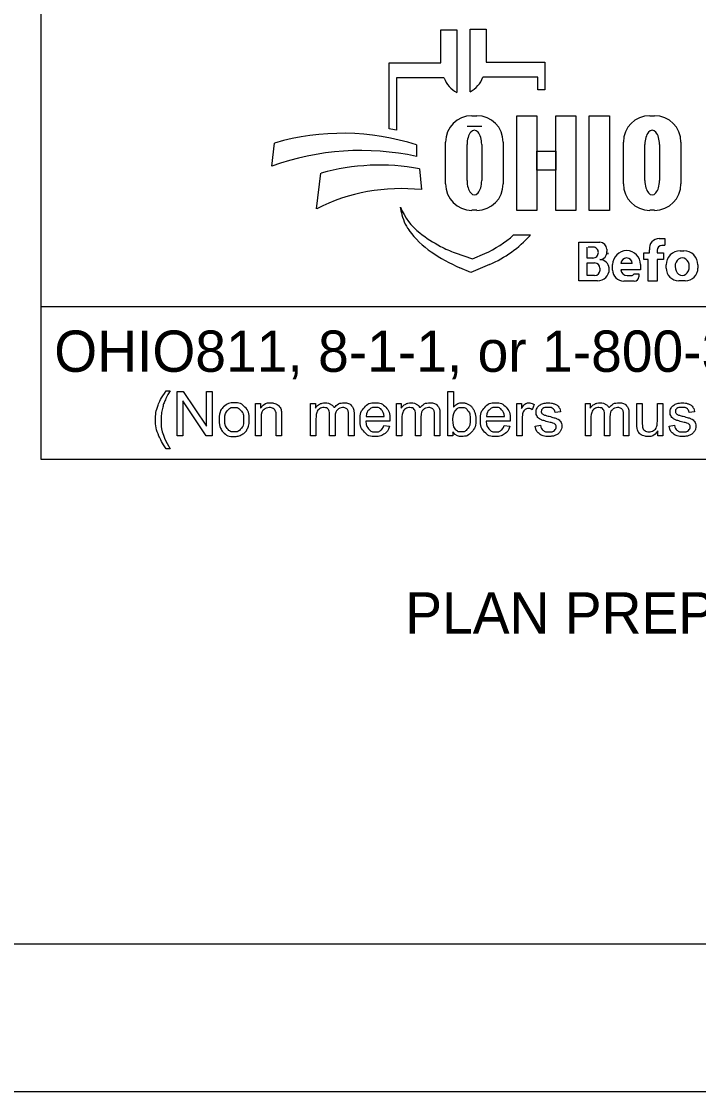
# Model space of a CAD drawing. Extents: x 0 to 81.5, y 0 to 35.2.
# Drawn here: x 2.311 to 4.607, y 0 to 3.629 of the extents above; entities that cross this region are included whole.
import ezdxf

# ---------------------------------------------------------------- set-up
doc = ezdxf.new("R2010")
doc.units = 0
for name, color, linetype in [('SH_Border', 7, 'Continuous'), ('SH_Cut_Line', 7, 'Continuous'), ('SH_Data', 7, 'Continuous'), ('SH_Text', 7, 'Continuous')]:
    doc.layers.add(name, color=color, linetype=linetype)

msp = doc.modelspace()

# ---------------------------------------------------------------- linework, layer by layer
at = {"layer": 'SH_Border'}
msp.add_lwpolyline([(1.5, 21.5), (33.5, 21.5), (33.5, 0.5), (1.5, 0.5)], close=True, dxfattribs=at)
at = {"layer": 'SH_Cut_Line'}
msp.add_lwpolyline([(0, 0), (34, 0), (34, 22), (0, 22)], close=True, dxfattribs=at)
at = {"layer": 'SH_Data'}
for p, q in [((2.3775, 2.1428), (2.3775, 4.4803)), ((6.6275, 2.6607), (2.3775, 2.6607)), ((6.6275, 2.1428), (2.3775, 2.1428))]:
    msp.add_line(p, q, dxfattribs=at)
at = {"layer": 'SH_Text'}
for p, q in [((3.7335, 3.4883), (3.7335, 3.5998)), ((3.7335, 3.5998), (3.7872, 3.5998)), ((3.7872, 3.5998), (3.7872, 3.3877)), ((3.8329, 3.39), (3.8329, 3.6021)), ((3.8329, 3.6021), (3.8865, 3.6021)), ((3.8865, 3.6021), (3.8865, 3.4906)), ((3.5576, 3.2644), (3.5576, 3.4883)), ((3.5576, 3.4883), (3.7335, 3.4883)), ((3.8865, 3.4906), (4.0857, 3.4906)), ((4.0857, 3.4906), (4.0857, 3.3968)), ((3.5828, 3.4369), (3.5828, 3.26)), ((3.7439, 3.4369), (3.5828, 3.4369)), ((4.0625, 3.4392), (3.8761, 3.4392)), ((4.0625, 3.3968), (4.0625, 3.4392)), ((4.0857, 3.3968), (4.0625, 3.3968)), ((3.8385, 3.3091), (3.8551, 3.3091)), ((4.4416, 3.3091), (4.4581, 3.3091)), ((3.8718, 3.2721), (3.822, 3.2721)), ((3.1602, 3.1381), (3.1696, 3.2162)), ((3.6509, 3.2097), (3.6509, 3.1709)), ((3.7491, 3.0776), (3.7491, 3.2196)), ((3.822, 3.089), (3.822, 3.2114)), ((3.8718, 3.2114), (3.8718, 3.089)), ((3.9445, 3.2196), (3.9445, 3.0776)), ((4.3521, 3.0776), (4.3521, 3.2196)), ((4.425, 3.089), (4.425, 3.2114)), ((4.4748, 3.2114), (4.4748, 3.089)), ((4.5476, 3.2196), (4.5476, 3.0776)), ((3.6608, 3.1291), (3.6671, 3.0582)), ((3.312, 2.9936), (3.3267, 3.1137)), ((3.5997, 2.9807), (3.5967, 2.9986)), ((3.8551, 2.9882), (3.8385, 2.9882)), ((4.4581, 2.9882), (4.4416, 2.9882)), ((3.98, 2.9048), (4.0375, 2.9048)), ((4.2013, 2.749), (4.2013, 2.8798)), ((4.2013, 2.8798), (4.2725, 2.8798)), ((4.4739, 2.8926), (4.4934, 2.8926)), ((4.4934, 2.8691), (4.4832, 2.8691)), ((4.4934, 2.8926), (4.4934, 2.8696)), ((3.7816, 2.8444), (3.841, 2.8239)), ((3.841, 2.8239), (3.8821, 2.8417)), ((4.2293, 2.8263), (4.2293, 2.8632)), ((4.2545, 2.8632), (4.2332, 2.8632)), ((4.2963, 2.856), (4.2963, 2.8481)), ((4.4213, 2.8212), (4.4213, 2.8442)), ((4.4213, 2.8442), (4.4406, 2.8442)), ((4.4406, 2.8442), (4.4406, 2.8546)), ((4.4667, 2.8526), (4.4667, 2.8442)), ((4.4667, 2.8442), (4.4883, 2.8442)), ((4.4883, 2.8442), (4.4883, 2.8212)), ((4.5451, 2.8508), (4.5573, 2.8508)), ((3.8983, 2.8044), (3.835, 2.7769)), ((4.2487, 2.8263), (4.2293, 2.8263)), ((4.2293, 2.7669), (4.2293, 2.8097)), ((4.2293, 2.8097), (4.2548, 2.8097)), ((4.3159, 2.7858), (4.3159, 2.8042)), ((4.3824, 2.8082), (4.3439, 2.8082)), ((4.4104, 2.8042), (4.4104, 2.7866)), ((4.4362, 2.8212), (4.4213, 2.8212)), ((4.4362, 2.7478), (4.4362, 2.8212)), ((4.4883, 2.8212), (4.4667, 2.8212)), ((4.4667, 2.8212), (4.4667, 2.7478)), ((4.4973, 2.7922), (4.4973, 2.8029)), ((4.6051, 2.8029), (4.6051, 2.7922)), ((3.835, 2.7769), (3.7976, 2.7934)), ((4.2546, 2.7669), (4.2293, 2.7669)), ((4.2729, 2.7916), (4.2729, 2.7853)), ((4.3043, 2.7887), (4.3043, 2.7884)), ((4.4104, 2.7866), (4.344, 2.7866)), ((4.3649, 2.7673), (4.379, 2.7673)), ((4.3876, 2.7729), (4.4045, 2.7729)), ((4.4045, 2.7729), (4.4045, 2.7631)), ((4.265, 2.749), (4.2013, 2.749)), ((4.3892, 2.7478), (4.3538, 2.7478)), ((4.4667, 2.7478), (4.4362, 2.7478)), ((4.5623, 2.7494), (4.5401, 2.7494))]:
    msp.add_line(p, q, dxfattribs=at)
for points in [[(3.991, 3.3081), (4.0589, 3.3081), (4.0589, 2.9881), (3.991, 2.9881)], [(4.1231, 3.3081), (4.1911, 3.3081), (4.1911, 2.9881), (4.1231, 2.9881)], [(4.2364, 3.3081), (4.3052, 3.3081), (4.3052, 2.9881), (4.2364, 2.9881)], [(4.0589, 3.1882), (4.1231, 3.1882), (4.1231, 3.1242), (4.0589, 3.1242)]]:
    msp.add_lwpolyline(points, close=True, dxfattribs=at)
for points in [[(2.8021, 2.3766), (2.8153, 2.3766)], [(2.8389, 2.2239), (2.8389, 2.3741), (2.8592, 2.3741), (2.9382, 2.2561), (2.9382, 2.3741), (2.9572, 2.3741), (2.9572, 2.2239), (2.9369, 2.2239), (2.8579, 2.3419), (2.8579, 2.2239), (2.8389, 2.2239)], [(3.7743, 2.2239), (3.7573, 2.2239), (3.7573, 2.3741), (3.7757, 2.3741), (3.7757, 2.3206)], [(3.1048, 2.2239), (3.1048, 2.3328), (3.1214, 2.3328), (3.1214, 2.3173)], [(3.2912, 2.2239), (3.2912, 2.3328), (3.3077, 2.3328), (3.3077, 2.3174)], [(3.5826, 2.2239), (3.5826, 2.3328), (3.5991, 2.3328), (3.5991, 2.3174)], [(3.9904, 2.2239), (3.9904, 2.3328), (4.007, 2.3328), (4.007, 2.3163)], [(4.0495, 2.3293), (4.043, 2.3122)], [(4.2236, 2.2239), (4.2236, 2.3328), (4.2401, 2.3328), (4.2401, 2.3174)], [(4.3979, 2.2654), (4.3979, 2.3328), (4.4164, 2.3328), (4.4164, 2.2724)], [(4.4676, 2.2745), (4.4676, 2.3328), (4.4861, 2.3328), (4.4861, 2.2239), (4.4696, 2.2239)], [(3.1932, 2.2908), (3.1932, 2.2239), (3.1748, 2.2239), (3.1748, 2.2901)], [(3.3743, 2.2871), (3.3743, 2.2239), (3.3559, 2.2239), (3.3559, 2.2946)], [(3.4388, 2.2986), (3.4388, 2.2239), (3.4203, 2.2239), (3.4203, 2.2924)], [(3.4799, 2.2887), (3.5406, 2.2887)], [(3.6657, 2.2871), (3.6657, 2.2239), (3.6473, 2.2239), (3.6473, 2.2946)], [(3.7301, 2.2986), (3.7301, 2.2239), (3.7117, 2.2239), (3.7117, 2.2924)], [(3.8879, 2.2887), (3.9486, 2.2887)], [(4.1394, 2.3046), (4.1213, 2.3022)], [(4.3067, 2.2871), (4.3067, 2.2239), (4.2883, 2.2239), (4.2883, 2.2946)], [(4.3711, 2.2986), (4.3711, 2.2239), (4.3527, 2.2239), (4.3527, 2.2924)], [(4.594, 2.3046), (4.5759, 2.3022)], [(3.1233, 2.2833), (3.1233, 2.2239), (3.1048, 2.2239)], [(3.3097, 2.2803), (3.3097, 2.2239), (3.2912, 2.2239)], [(3.56, 2.2736), (3.4788, 2.2736)], [(3.5404, 2.2591), (3.5595, 2.2567)], [(3.601, 2.2803), (3.601, 2.2239), (3.5826, 2.2239)], [(3.968, 2.2736), (3.8868, 2.2736)], [(3.9484, 2.2591), (3.9675, 2.2567)], [(4.0088, 2.2809), (4.0088, 2.2239), (3.9904, 2.2239)], [(4.053, 2.2564), (4.0712, 2.2593)], [(4.242, 2.2803), (4.242, 2.2239), (4.2236, 2.2239)], [(4.5076, 2.2564), (4.5258, 2.2593)], [(3.7743, 2.2375), (3.7743, 2.2239)], [(4.4696, 2.2239), (4.4696, 2.24)], [(2.8153, 2.1798), (2.8021, 2.1798)]]:
    msp.add_lwpolyline(points, dxfattribs=at)
for centre, radius, start, end in [((3.8353, 3.4736), 0.0985, 201.9296, 240.7469), ((3.7847, 3.476), 0.0985, 299.2531, 338.0704), ((3.8385, 3.2196), 0.0895, 90, 180), ((3.8551, 3.2196), 0.0895, 0, 90), ((4.4416, 3.2196), 0.0895, 90, 180), ((4.4581, 3.2196), 0.0895, 0, 90), ((3.3997, 2.4302), 0.8191, 72.1402, 106.3144), ((3.4295, 2.4554), 0.8191, 79.2074, 81.0007), ((3.4628, 2.2991), 0.8919, 77.8238, 109.8274), ((3.5267, 2.4094), 0.7322, 79.44, 105.8467), ((3.5987, 2.4262), 0.6357, 83.8248, 116.8021), ((3.8385, 3.0776), 0.0895, 180, 270), ((3.8551, 3.0776), 0.0895, 270, 0), ((4.4416, 3.0776), 0.0895, 180, 270), ((4.4581, 3.0776), 0.0895, 270, 0), ((3.7841, 3.0707), 0.2008, 201.0457, 232.5314), ((3.741, 3.0048), 0.1433, 189.6817, 216.0884), ((3.8747, 3.1022), 0.3088, 216.0884, 235.7167), ((3.9766, 3.3219), 0.5173, 232.5314, 241.794), ((3.7387, 3.1722), 0.3602, 293.4582, 312.0712), ((3.7387, 3.1722), 0.401, 293.4582, 317.8286), ((4.2725, 2.856), 0.0238, 0, 90), ((4.4739, 2.859), 0.0335, 90, 187.5187), ((4.4832, 2.8526), 0.0165, 90, 180), ((4.0412, 3.3465), 0.6044, 235.7167, 246.2325), ((3.8914, 3.1631), 0.3371, 241.794, 250.9821), ((4.2487, 2.845), 0.0187, 270, 2.0582), ((4.2505, 2.8463), 0.0169, 357.8325, 90), ((4.2721, 2.8453), 0.0243, 270, 6.6529), ((4.2827, 2.8438), 0.0175, 347.4023, 0), ((4.3631, 2.8042), 0.0473, 0, 180), ((4.5451, 2.8029), 0.0478, 90, 180), ((4.5573, 2.8029), 0.0478, 0, 90), ((4.2548, 2.7916), 0.0181, 0, 90), ((4.2722, 2.7889), 0.0321, 4.0748, 90), ((4.2714, 2.7887), 0.033, 0, 11.7502), ((4.3632, 2.8072), 0.0193, 2.9632, 177.0368), ((4.2546, 2.7853), 0.0184, 270, 0), ((4.265, 2.7884), 0.0393, 270, 0), ((4.3538, 2.7858), 0.038, 180, 270), ((4.3649, 2.7883), 0.021, 184.827, 270), ((4.379, 2.7767), 0.00938, 270, 335.9979), ((4.3892, 2.7631), 0.0152, 270, 0), ((4.5401, 2.7922), 0.0428, 180, 270), ((4.5623, 2.7922), 0.0428, 270, 0)]:
    msp.add_arc(centre, radius, start, end, dxfattribs=at)
for centre, major_axis, ratio, start_param, end_param in [((3.8469, 3.2114), (0, 0.0484), 0.514403, 4.712389, 7.853982), ((4.4499, 3.2114), (0, 0.0484), 0.514403, 4.712389, 7.853982), ((3.8469, 3.089), (0, 0.0484), 0.514403, 1.570796, 4.712389), ((4.4499, 3.089), (0, 0.0484), 0.514403, 1.570796, 4.712389), ((4.5517, 2.7976), (0, 0.029), 0.832186, 4.712389, 7.853982), ((4.5517, 2.7976), (0, 0.0302), 0.797287, 1.570796, 4.712389)]:
    msp.add_ellipse(centre, major_axis=major_axis, ratio=ratio, start_param=start_param, end_param=end_param, dxfattribs=at)
for points in [[(2.8021, 2.1798), (2.7869, 2.199), (2.7763, 2.2248), (2.7657, 2.2506), (2.7657, 2.2783), (2.7657, 2.3026), (2.7736, 2.325), (2.7829, 2.3509), (2.8021, 2.3766)], [(2.8153, 2.3766), (2.8029, 2.3553), (2.7989, 2.3462), (2.7927, 2.332), (2.7891, 2.3167), (2.7847, 2.2975), (2.7847, 2.2782), (2.7847, 2.2289), (2.8153, 2.1798)], [(2.9814, 2.2783), (2.9814, 2.3085), (2.9981, 2.3231), (3.0122, 2.3352), (3.0323, 2.3352), (3.0547, 2.3352), (3.069, 2.3205), (3.0832, 2.3058), (3.0832, 2.2799), (3.0832, 2.2589), (3.0769, 2.2469), (3.0706, 2.2348), (3.0586, 2.2282), (3.0466, 2.2215), (3.0323, 2.2215), (3.0095, 2.2215), (2.9954, 2.2362), (2.9814, 2.2508), (2.9814, 2.2783)], [(3.1214, 2.3173), (3.1334, 2.3352), (3.156, 2.3352), (3.1659, 2.3352), (3.1741, 2.3316), (3.1823, 2.3281), (3.1864, 2.3224), (3.1905, 2.3166), (3.1922, 2.3087), (3.1932, 2.3036), (3.1932, 2.2908)], [(3.3077, 2.3174), (3.3128, 2.3254), (3.3214, 2.3303), (3.3299, 2.3352), (3.3407, 2.3352), (3.3528, 2.3352), (3.3606, 2.3301), (3.3683, 2.3251), (3.3715, 2.3161), (3.3844, 2.3352), (3.4051, 2.3352), (3.4213, 2.3352), (3.43, 2.3262), (3.4388, 2.3172), (3.4388, 2.2986)], [(3.5595, 2.2567), (3.555, 2.24), (3.5428, 2.2307), (3.5306, 2.2215), (3.5117, 2.2215), (3.4878, 2.2215), (3.4738, 2.2362), (3.4598, 2.2509), (3.4598, 2.2774), (3.4598, 2.3049), (3.474, 2.32), (3.4881, 2.3352), (3.5106, 2.3352), (3.5324, 2.3352), (3.5463, 2.3203), (3.5601, 2.3055), (3.5601, 2.2785), (3.5601, 2.2769), (3.56, 2.2736)], [(3.5991, 2.3174), (3.6042, 2.3254), (3.6127, 2.3303), (3.6212, 2.3352), (3.6321, 2.3352), (3.6442, 2.3352), (3.6519, 2.3301), (3.6597, 2.3251), (3.6628, 2.3161), (3.6758, 2.3352), (3.6965, 2.3352), (3.7127, 2.3352), (3.7214, 2.3262), (3.7301, 2.3172), (3.7301, 2.2986)], [(3.7757, 2.3206), (3.7874, 2.3352), (3.8055, 2.3352), (3.8155, 2.3352), (3.8245, 2.3311), (3.8335, 2.3271), (3.8392, 2.3198), (3.845, 2.3124), (3.8483, 2.3021), (3.8516, 2.2918), (3.8516, 2.28), (3.8516, 2.252), (3.8378, 2.2368), (3.8239, 2.2215), (3.8046, 2.2215), (3.7853, 2.2215), (3.7743, 2.2375)], [(3.9675, 2.2567), (3.963, 2.24), (3.9508, 2.2307), (3.9386, 2.2215), (3.9196, 2.2215), (3.8958, 2.2215), (3.8818, 2.2362), (3.8678, 2.2509), (3.8678, 2.2774), (3.8678, 2.3049), (3.882, 2.32), (3.8961, 2.3352), (3.9186, 2.3352), (3.9404, 2.3352), (3.9543, 2.3203), (3.9681, 2.3055), (3.9681, 2.2785), (3.9681, 2.2769), (3.968, 2.2736)], [(4.007, 2.3163), (4.0133, 2.3278), (4.0187, 2.3315), (4.0241, 2.3352), (4.0305, 2.3352), (4.0398, 2.3352), (4.0495, 2.3293)], [(4.0712, 2.2593), (4.0727, 2.2483), (4.0798, 2.2425), (4.0868, 2.2366), (4.0995, 2.2366), (4.1122, 2.2366), (4.1184, 2.2418), (4.1245, 2.247), (4.1245, 2.254), (4.1245, 2.2602), (4.1191, 2.2638), (4.1153, 2.2663), (4.1002, 2.2701), (4.0799, 2.2752), (4.072, 2.2789), (4.0642, 2.2827), (4.0601, 2.2893), (4.0561, 2.2959), (4.0561, 2.3038), (4.0561, 2.3111), (4.0594, 2.3173), (4.0628, 2.3235), (4.0685, 2.3276), (4.0728, 2.3308), (4.0803, 2.333), (4.0877, 2.3352), (4.0962, 2.3352), (4.109, 2.3352), (4.1187, 2.3315), (4.1284, 2.3278), (4.133, 2.3215), (4.1377, 2.3152), (4.1394, 2.3046)], [(4.2401, 2.3174), (4.2452, 2.3254), (4.2537, 2.3303), (4.2622, 2.3352), (4.2731, 2.3352), (4.2852, 2.3352), (4.2929, 2.3301), (4.3007, 2.3251), (4.3038, 2.3161), (4.3168, 2.3352), (4.3375, 2.3352), (4.3537, 2.3352), (4.3624, 2.3262), (4.3711, 2.3172), (4.3711, 2.2986)], [(4.5258, 2.2593), (4.5273, 2.2483), (4.5343, 2.2425), (4.5414, 2.2366), (4.554, 2.2366), (4.5668, 2.2366), (4.5729, 2.2418), (4.5791, 2.247), (4.5791, 2.254), (4.5791, 2.2602), (4.5736, 2.2638), (4.5698, 2.2663), (4.5548, 2.2701), (4.5345, 2.2752), (4.5266, 2.2789), (4.5188, 2.2827), (4.5147, 2.2893), (4.5107, 2.2959), (4.5107, 2.3038), (4.5107, 2.3111), (4.514, 2.3173), (4.5173, 2.3235), (4.5231, 2.3276), (4.5274, 2.3308), (4.5348, 2.333), (4.5423, 2.3352), (4.5508, 2.3352), (4.5636, 2.3352), (4.5733, 2.3315), (4.583, 2.3278), (4.5876, 2.3215), (4.5922, 2.3152), (4.594, 2.3046)], [(3.0003, 2.2783), (3.0003, 2.2574), (3.0094, 2.247), (3.0185, 2.2366), (3.0323, 2.2366), (3.046, 2.2366), (3.0551, 2.2471), (3.0642, 2.2575), (3.0642, 2.279), (3.0642, 2.2991), (3.0551, 2.3095), (3.0459, 2.3199), (3.0323, 2.3199), (3.0185, 2.3199), (3.0094, 2.3096), (3.0003, 2.2992), (3.0003, 2.2783)], [(3.1748, 2.2901), (3.1748, 2.3013), (3.1726, 2.3069), (3.1705, 2.3125), (3.165, 2.3158), (3.1595, 2.3191), (3.1521, 2.3191), (3.1404, 2.3191), (3.1318, 2.3117), (3.1233, 2.3042), (3.1233, 2.2833)], [(3.3559, 2.2946), (3.3559, 2.3069), (3.3514, 2.313), (3.3469, 2.3191), (3.3366, 2.3191), (3.3288, 2.3191), (3.3222, 2.315), (3.3156, 2.311), (3.3126, 2.3031), (3.3097, 2.2952), (3.3097, 2.2803)], [(3.4203, 2.2924), (3.4203, 2.3035), (3.4185, 2.3083), (3.4168, 2.3132), (3.412, 2.3162), (3.4073, 2.3191), (3.401, 2.3191), (3.3895, 2.3191), (3.3819, 2.3115), (3.3743, 2.3039), (3.3743, 2.2871)], [(3.5406, 2.2887), (3.5394, 2.3025), (3.5337, 2.3094), (3.5249, 2.3201), (3.5108, 2.3201), (3.4981, 2.3201), (3.4894, 2.3115), (3.4808, 2.303), (3.4799, 2.2887)], [(3.6473, 2.2946), (3.6473, 2.3069), (3.6428, 2.313), (3.6383, 2.3191), (3.628, 2.3191), (3.6202, 2.3191), (3.6136, 2.315), (3.607, 2.311), (3.604, 2.3031), (3.601, 2.2952), (3.601, 2.2803)], [(3.7117, 2.2924), (3.7117, 2.3035), (3.7099, 2.3083), (3.7081, 2.3132), (3.7034, 2.3162), (3.6987, 2.3191), (3.6923, 2.3191), (3.6809, 2.3191), (3.6733, 2.3115), (3.6657, 2.3039), (3.6657, 2.2871)], [(3.7741, 2.2792), (3.7741, 2.2596), (3.7794, 2.2509), (3.7881, 2.2366), (3.8029, 2.2366), (3.815, 2.2366), (3.8238, 2.2471), (3.8326, 2.2576), (3.8326, 2.2784), (3.8326, 2.2998), (3.8241, 2.3099), (3.8157, 2.3201), (3.8038, 2.3201), (3.7917, 2.3201), (3.7829, 2.3096), (3.7741, 2.299), (3.7741, 2.2792)], [(3.9486, 2.2887), (3.9474, 2.3025), (3.9417, 2.3094), (3.9328, 2.3201), (3.9188, 2.3201), (3.9061, 2.3201), (3.8974, 2.3115), (3.8888, 2.303), (3.8879, 2.2887)], [(4.043, 2.3122), (4.0363, 2.3162), (4.0295, 2.3162), (4.0235, 2.3162), (4.0187, 2.3125), (4.0139, 2.3089), (4.0119, 2.3024), (4.0088, 2.2926), (4.0088, 2.2809)], [(4.1213, 2.3022), (4.1201, 2.3106), (4.1142, 2.3153), (4.1083, 2.3201), (4.0975, 2.3201), (4.0848, 2.3201), (4.0794, 2.3159), (4.0739, 2.3116), (4.0739, 2.306), (4.0739, 2.3024), (4.0762, 2.2995), (4.0785, 2.2966), (4.0833, 2.2946), (4.086, 2.2936), (4.0996, 2.2899), (4.1192, 2.2847), (4.1269, 2.2813), (4.1347, 2.278), (4.1391, 2.2717), (4.1435, 2.2653), (4.1435, 2.2559), (4.1435, 2.2467), (4.1381, 2.2386), (4.1327, 2.2304), (4.1226, 2.226), (4.1124, 2.2215), (4.0996, 2.2215), (4.0784, 2.2215), (4.0672, 2.2303), (4.0561, 2.2391), (4.053, 2.2564)], [(4.2883, 2.2946), (4.2883, 2.3069), (4.2838, 2.313), (4.2793, 2.3191), (4.269, 2.3191), (4.2612, 2.3191), (4.2546, 2.315), (4.248, 2.311), (4.245, 2.3031), (4.242, 2.2952), (4.242, 2.2803)], [(4.3527, 2.2924), (4.3527, 2.3035), (4.3509, 2.3083), (4.3491, 2.3132), (4.3444, 2.3162), (4.3397, 2.3191), (4.3333, 2.3191), (4.3219, 2.3191), (4.3143, 2.3115), (4.3067, 2.3039), (4.3067, 2.2871)], [(4.5759, 2.3022), (4.5747, 2.3106), (4.5688, 2.3153), (4.5629, 2.3201), (4.5521, 2.3201), (4.5394, 2.3201), (4.5339, 2.3159), (4.5285, 2.3116), (4.5285, 2.306), (4.5285, 2.3024), (4.5308, 2.2995), (4.533, 2.2966), (4.5378, 2.2946), (4.5406, 2.2936), (4.5542, 2.2899), (4.5737, 2.2847), (4.5815, 2.2813), (4.5893, 2.278), (4.5937, 2.2717), (4.5981, 2.2653), (4.5981, 2.2559), (4.5981, 2.2467), (4.5927, 2.2386), (4.5873, 2.2304), (4.5772, 2.226), (4.567, 2.2215), (4.5542, 2.2215), (4.5329, 2.2215), (4.5218, 2.2303), (4.5107, 2.2391), (4.5076, 2.2564)], [(3.4788, 2.2736), (3.4799, 2.2557), (3.489, 2.2462), (3.4981, 2.2366), (3.5117, 2.2366), (3.5219, 2.2366), (3.5291, 2.242), (3.5362, 2.2473), (3.5404, 2.2591)], [(3.8868, 2.2736), (3.8879, 2.2557), (3.897, 2.2462), (3.9061, 2.2366), (3.9197, 2.2366), (3.9299, 2.2366), (3.937, 2.242), (3.9442, 2.2473), (3.9484, 2.2591)], [(4.4696, 2.24), (4.4569, 2.2215), (4.4351, 2.2215), (4.4255, 2.2215), (4.4171, 2.2252), (4.4088, 2.2289), (4.4047, 2.2345), (4.4007, 2.2401), (4.3991, 2.2482), (4.3979, 2.2536), (4.3979, 2.2654)], [(4.4164, 2.2724), (4.4164, 2.258), (4.4175, 2.253), (4.4192, 2.2457), (4.4249, 2.2416), (4.4305, 2.2374), (4.4388, 2.2374), (4.4471, 2.2374), (4.4543, 2.2417), (4.4616, 2.2459), (4.4646, 2.2533), (4.4676, 2.2606), (4.4676, 2.2745)]]:
    msp.add_open_spline(points, degree=3, dxfattribs=at)

# ---------------------------------------------------------------- texts
for s, p in [('OHIO811, 8-1-1, or 1-800-362-2764', (2.422, 2.4406)), ('PLAN PREPARED BY:', (3.6125, 1.553))]:
    msp.add_text(s, height=0.14, dxfattribs=at).set_placement(p)

doc.saveas('drawing.dxf')
